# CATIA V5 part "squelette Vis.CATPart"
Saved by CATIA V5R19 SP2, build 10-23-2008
Part number: Vis
Publications: "Plan xy", "Droite.1"
Bounding box of the stored display mesh (mm): x 0 to 0, y 0 to 150, z 0 to 0
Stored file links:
  G:\EU_thinkMotion\CFAO_2010\MMS_groupe3\MMS_groupe3\A reprendre\mmugnier\Systeme_Cric_Y\Systeme_Cric_Y\squelette Vis.CATPart
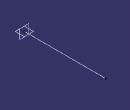
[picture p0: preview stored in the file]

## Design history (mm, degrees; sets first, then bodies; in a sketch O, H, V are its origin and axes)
Set1
  Line1: type Normal, RefPoint {point type Coord, X 0, Y 0, Z 0}, RefSkin zx-plane, Start 0, End 150
Body1 (main body)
